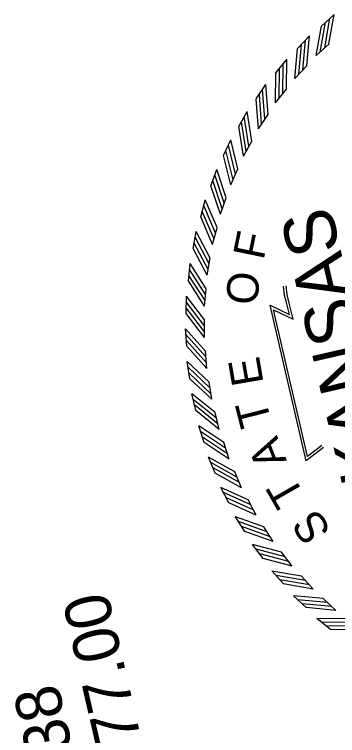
# Model space of a CAD drawing. Extents: x 634644 to 1109508, y 286699 to 700437.
# Drawn here: x 1109057.9 to 1109100, y 700243.2 to 700337.3 of the extents above; entities that cross this region are included whole.
import ezdxf

# ---------------------------------------------------------------- set-up
doc = ezdxf.new("R2010")
doc.units = 0
doc.layers.add('Level 24', color=7, linetype='Continuous')
doc.layers.add('R_Border', color=7, linetype='Continuous')

msp = doc.modelspace()

# ---------------------------------------------------------------- linework, layer by layer
at = {"layer": 'R_Border'}
for p, q in [((1109097.929, 700335.765), (1109099.611, 700337.277)), ((1109094.836, 700332.83), (1109096.387, 700334.476)), ((1109097.242, 700331.912), (1109098.928, 700333.427)), ((1109091.995, 700329.65), (1109093.406, 700331.418)), ((1109094.469, 700328.933), (1109096.025, 700330.583)), ((1109089.428, 700326.246), (1109090.687, 700328.125)), ((1109091.952, 700325.736), (1109093.366, 700327.509)), ((1109087.15, 700322.642), (1109088.25, 700324.618)), ((1109089.708, 700322.342), (1109090.971, 700324.225)), ((1109085.177, 700318.862), (1109086.111, 700320.922)), ((1109087.752, 700318.774), (1109088.854, 700320.755)), ((1109083.524, 700314.932), (1109084.284, 700317.062)), ((1109086.096, 700315.057), (1109087.032, 700317.122)), ((1109082.2, 700310.878), (1109082.782, 700313.064)), ((1109084.754, 700311.216), (1109085.516, 700313.351)), ((1109083.733, 700307.277), (1109084.316, 700309.468)), ((1109081.216, 700306.73), (1109081.615, 700308.956)), ((1109083.041, 700303.267), (1109083.441, 700305.499)), ((1109080.578, 700302.514), (1109080.792, 700304.766)), ((1109082.683, 700299.214), (1109082.897, 700301.471)), ((1109080.29, 700298.26), (1109080.317, 700300.522)), ((1109082.66, 700295.145), (1109082.687, 700297.412)), ((1109080.355, 700293.997), (1109080.195, 700296.253)), ((1109082.974, 700291.088), (1109082.814, 700293.349)), ((1109080.771, 700289.753), (1109080.425, 700291.989)), ((1109083.621, 700287.071), (1109083.275, 700289.311)), ((1109081.559, 700285.587), (1109081.05, 700287.791)), ((1109084.598, 700283.121), (1109084.088, 700285.33)), ((1109082.645, 700281.442), (1109081.936, 700283.59)), ((1109085.898, 700279.265), (1109085.188, 700281.418)), ((1109084.09, 700277.43), (1109083.207, 700279.512)), ((1109087.512, 700275.529), (1109086.626, 700277.616)), ((1109085.862, 700273.552), (1109084.809, 700275.554)), ((1109089.429, 700271.94), (1109088.374, 700273.947)), ((1109087.948, 700269.833), (1109086.733, 700271.741)), ((1109091.636, 700268.521), (1109090.418, 700270.434)), ((1109090.333, 700266.299), (1109088.965, 700268.101)), ((1109094.117, 700265.296), (1109092.746, 700267.102)), ((1109093.003, 700262.974), (1109091.491, 700264.657)), ((1109096.856, 700262.288), (1109095.341, 700263.974)), ((1109095.938, 700259.881), (1109094.292, 700261.433)), ((1109099.835, 700259.515), (1109098.185, 700261.07)), ((1109099.118, 700257.041), (1109097.35, 700258.452))]:
    msp.add_line(p, q, dxfattribs=at)
for points in [[(1109098.36, 700332.928), (1109099.046, 700336.781)], [(1109098.925, 700333.427), (1109099.611, 700337.28)], [(1109097.241, 700331.908), (1109097.928, 700335.762)], [(1109097.787, 700332.39), (1109098.474, 700336.243)], [(1109096.022, 700330.582), (1109096.388, 700334.479)], [(1109095.5, 700330.039), (1109095.866, 700333.935)], [(1109094.469, 700328.93), (1109094.835, 700332.827)], [(1109094.973, 700329.455), (1109095.339, 700333.352)], [(1109092.888, 700326.923), (1109092.931, 700330.836)], [(1109093.363, 700327.507), (1109093.406, 700331.421)], [(1109092.412, 700326.298), (1109092.454, 700330.211)], [(1109091.952, 700325.733), (1109091.995, 700329.646)], [(1109090.968, 700324.224), (1109090.687, 700328.128)], [(1109090.542, 700323.602), (1109090.262, 700327.506)], [(1109089.708, 700322.339), (1109089.428, 700326.242)], [(1109090.119, 700322.94), (1109089.839, 700326.843)], [(1109088.852, 700320.754), (1109088.25, 700324.621)], [(1109088.112, 700319.404), (1109087.51, 700323.271)], [(1109088.479, 700320.099), (1109087.877, 700323.966)], [(1109087.752, 700318.771), (1109087.15, 700322.638)], [(1109087.029, 700317.12), (1109086.11, 700320.925)], [(1109086.404, 700315.714), (1109085.484, 700319.518)], [(1109086.712, 700316.437), (1109085.793, 700320.241)], [(1109086.097, 700315.054), (1109085.178, 700318.858)], [(1109085.513, 700313.349), (1109084.283, 700317.065)], [(1109085.253, 700312.642), (1109084.023, 700316.357)], [(1109084.755, 700311.212), (1109083.525, 700314.928)], [(1109085.006, 700311.896), (1109083.776, 700315.611)], [(1109084.314, 700309.466), (1109082.781, 700313.067)], [(1109084.113, 700308.739), (1109082.58, 700312.34)], [(1109083.928, 700307.975), (1109082.395, 700311.577)], [(1109083.734, 700307.274), (1109082.202, 700310.875)], [(1109083.299, 700304.756), (1109081.474, 700308.218)], [(1109083.439, 700305.496), (1109081.614, 700308.959)], [(1109083.178, 700303.979), (1109081.353, 700307.442)], [(1109083.043, 700303.264), (1109081.218, 700306.726)], [(1109082.895, 700301.468), (1109080.79, 700304.768)], [(1109082.817, 700300.719), (1109080.712, 700304.019)], [(1109082.685, 700299.211), (1109080.58, 700302.511)], [(1109082.76, 700299.935), (1109080.655, 700303.235)], [(1109098.205, 700280.781), (1109095.932, 700279.019), (1109091.228, 700299.343), (1109093.754, 700298.137), (1109093.417, 700299.513), (1109093.136, 700300.664), (1109092.995, 700301.845)], [(1109098.003, 700281.042), (1109096.138, 700279.596), (1109091.704, 700298.749), (1109094.24, 700297.539), (1109093.738, 700299.592), (1109093.461, 700300.723), (1109093.323, 700301.884)], [(1109082.67, 700296.656), (1109080.3, 700299.77)], [(1109082.686, 700297.409), (1109080.316, 700300.524)], [(1109082.678, 700295.87), (1109080.308, 700298.985)], [(1109082.662, 700295.142), (1109080.292, 700298.257)], [(1109082.812, 700293.347), (1109080.193, 700296.255)], [(1109082.858, 700292.594), (1109080.239, 700295.503)], [(1109082.931, 700291.812), (1109080.312, 700294.72)], [(1109082.976, 700291.085), (1109080.357, 700293.994)], [(1109083.274, 700289.308), (1109080.423, 700291.99)], [(1109083.382, 700288.563), (1109080.532, 700291.245)], [(1109083.519, 700287.789), (1109080.669, 700290.471)], [(1109083.624, 700287.068), (1109080.773, 700289.75)], [(1109084.087, 700285.327), (1109081.048, 700287.792)], [(1109084.25, 700284.591), (1109081.211, 700287.057)], [(1109084.444, 700283.829), (1109081.404, 700286.295)], [(1109084.601, 700283.118), (1109081.561, 700285.584)], [(1109085.187, 700281.415), (1109081.934, 700283.591)], [(1109085.417, 700280.697), (1109082.164, 700282.873)], [(1109085.679, 700279.956), (1109082.426, 700282.133)], [(1109085.901, 700279.263), (1109082.648, 700281.439)], [(1109086.626, 700277.613), (1109083.204, 700279.514)], [(1109086.914, 700276.917), (1109083.492, 700278.817)], [(1109087.237, 700276.2), (1109083.815, 700278.101)], [(1109087.515, 700275.528), (1109084.094, 700277.428)], [(1109088.374, 700273.944), (1109084.807, 700275.555)], [(1109088.718, 700273.273), (1109085.151, 700274.885)], [(1109089.099, 700272.586), (1109085.532, 700274.197)], [(1109089.432, 700271.939), (1109085.865, 700273.55)], [(1109090.418, 700270.431), (1109086.731, 700271.742)], [(1109090.817, 700269.791), (1109087.129, 700271.103)], [(1109091.254, 700269.138), (1109087.566, 700270.449)], [(1109091.639, 700268.52), (1109087.951, 700269.831)], [(1109092.746, 700267.099), (1109088.963, 700268.101)], [(1109093.196, 700266.495), (1109089.413, 700267.497)], [(1109093.685, 700265.879), (1109089.902, 700266.882)], [(1109094.12, 700265.296), (1109090.337, 700266.298)], [(1109095.341, 700263.971), (1109091.488, 700264.657)], [(1109095.84, 700263.406), (1109091.987, 700264.092)], [(1109096.378, 700262.833), (1109092.525, 700263.519)], [(1109096.86, 700262.287), (1109093.007, 700262.973)], [(1109098.186, 700261.067), (1109094.289, 700261.433)], [(1109098.729, 700260.545), (1109094.833, 700260.911)], [(1109099.313, 700260.019), (1109095.416, 700260.385)], [(1109099.838, 700259.515), (1109095.941, 700259.881)], [(1109101.261, 700258.409), (1109097.347, 700258.452)], [(1109101.845, 700257.934), (1109097.932, 700257.976)], [(1109102.47, 700257.457), (1109098.557, 700257.5)], [(1109103.035, 700256.998), (1109099.122, 700257.041)]]:
    msp.add_lwpolyline(points, dxfattribs=at)

# ---------------------------------------------------------------- texts
at = {"layer": 'Level 24'}
for s, p in [('PROP. FL OUTLET RT = 877.00', (1109096.296, 700148.166)), ('PROP. FL INLET LT = 878.38', (1109087.527, 700146.141))]:
    msp.add_text(s, height=6, rotation=103.0044, dxfattribs=at).set_placement(p)
at = {"layer": 'R_Border'}
for s, height, rotation, p in [('ARKANSAS', 6.7161, 103, (1109110.1, 700264.788)), ('F', 4.115, 78.36282, (1109090.392, 700305.129)), ('O', 4.115, 84.2218, (1109089.526, 700299.238)), ('E', 4.115, 99.67203, (1109090.399, 700289.185)), ('T', 4.115, 104.47887, (1109091.462, 700284.025)), ('A', 4.115, 111.67877, (1109093.455, 700279.031)), ('T', 4.115, 119.90148, (1109095.85, 700274.456)), ('S', 4.115, 122.77256, (1109099.316, 700269.886))]:
    msp.add_text(s, height=height, rotation=rotation, dxfattribs=at).set_placement(p)

doc.saveas('drawing.dxf')
